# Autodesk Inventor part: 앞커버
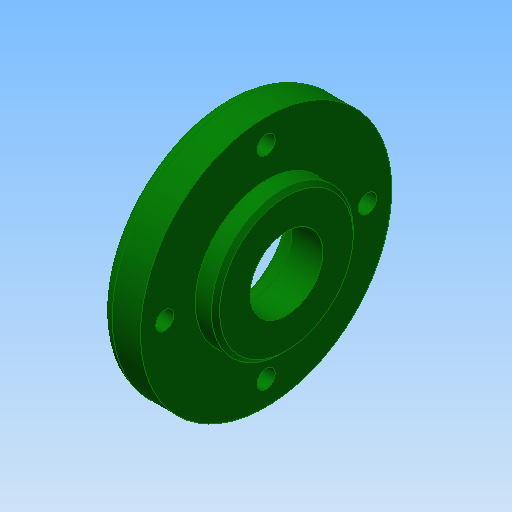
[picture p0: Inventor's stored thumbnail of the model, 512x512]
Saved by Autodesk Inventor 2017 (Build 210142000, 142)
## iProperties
Created: 2015-12
Part Number: 앞커버
Document SubType Name: Modeling
Designer: mdu
Density: 2.71 g/cm^3
Material: 알루미늄 6061
Appearance: 진녹색
Author: mdu
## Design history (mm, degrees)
sketch "스케치1"
  geometry: L1 (-7.5, 0)-(7.5, 0); L2 (-7.5, 0)-(-7.5, 31); L3 (-7.5, 31)-(2.5, 31); L4 (2.5, 31)-(2.5, 17.5); L5 (2.5, 17.5)-(7.5, 17.5); L6 (7.5, 17.5)-(7.5, 0); 2 further points
  constraints: 12 end point, 3 perpendicular, 1 coincident, 1 horizontal, 1 midpoint, 1 parallel
  dimensions: "d0" = 15 distance of L1.start L1.end; "d1" = 62 diameter of L3 L1; "d2" = 35 diameter of L5 L1; "d5" = 10 distance of L2.end L3.end
revolve "회전1" sketch "스케치1" stored, may be unused: angle "d6" = 90 deg
sketch "스케치2" dims "d42" = 50
  geometry: 3 further points
  constraints: 2 vertical alignment, 1 coincident, 2 other
hole "구멍1" sketch "스케치2" at (0, 25) diameter "d8" = 4.5; stored, may be unused: countersink angle "d12" = 90 deg, drill point angle "d14" = 118 deg; dims "d9" = 6, "d10" = 8, "d11" = 4.4, "d13" = 8
hole "구멍2" diameter "d20" = 18; stored, may be unused: countersink angle "d24" = 90 deg, drill point angle "d26" = 0 deg; dims "d18" = 10, "d19" = 10, "d21" = 6, "d22" = 8, "d23" = 4.4, "d25" = 8
hole "구멍3" diameter "d34" = 30; stored, may be unused: countersink angle "d38" = 90 deg, drill point angle "d40" = 0 deg; dims "d32" = 10, "d33" = 10, "d35" = 6, "d36" = 4, "d37" = 2, "d39" = 7.3
fillet "모깎기1" dims "d27" = 3, "d41" = 0.3
chamfer "모따기1" distance "d29" = 0.7; stored, may be unused: second distance "d30" = 2, angle "d31" = 30 deg
chamfer "모따기2" distance "d44" = 1; stored, may be unused: second distance "d45" = 2, angle "d46" = 45 deg
node "솔리드1"
pattern_circular "원형 패턴1" dims angle "d16" = 360 deg
